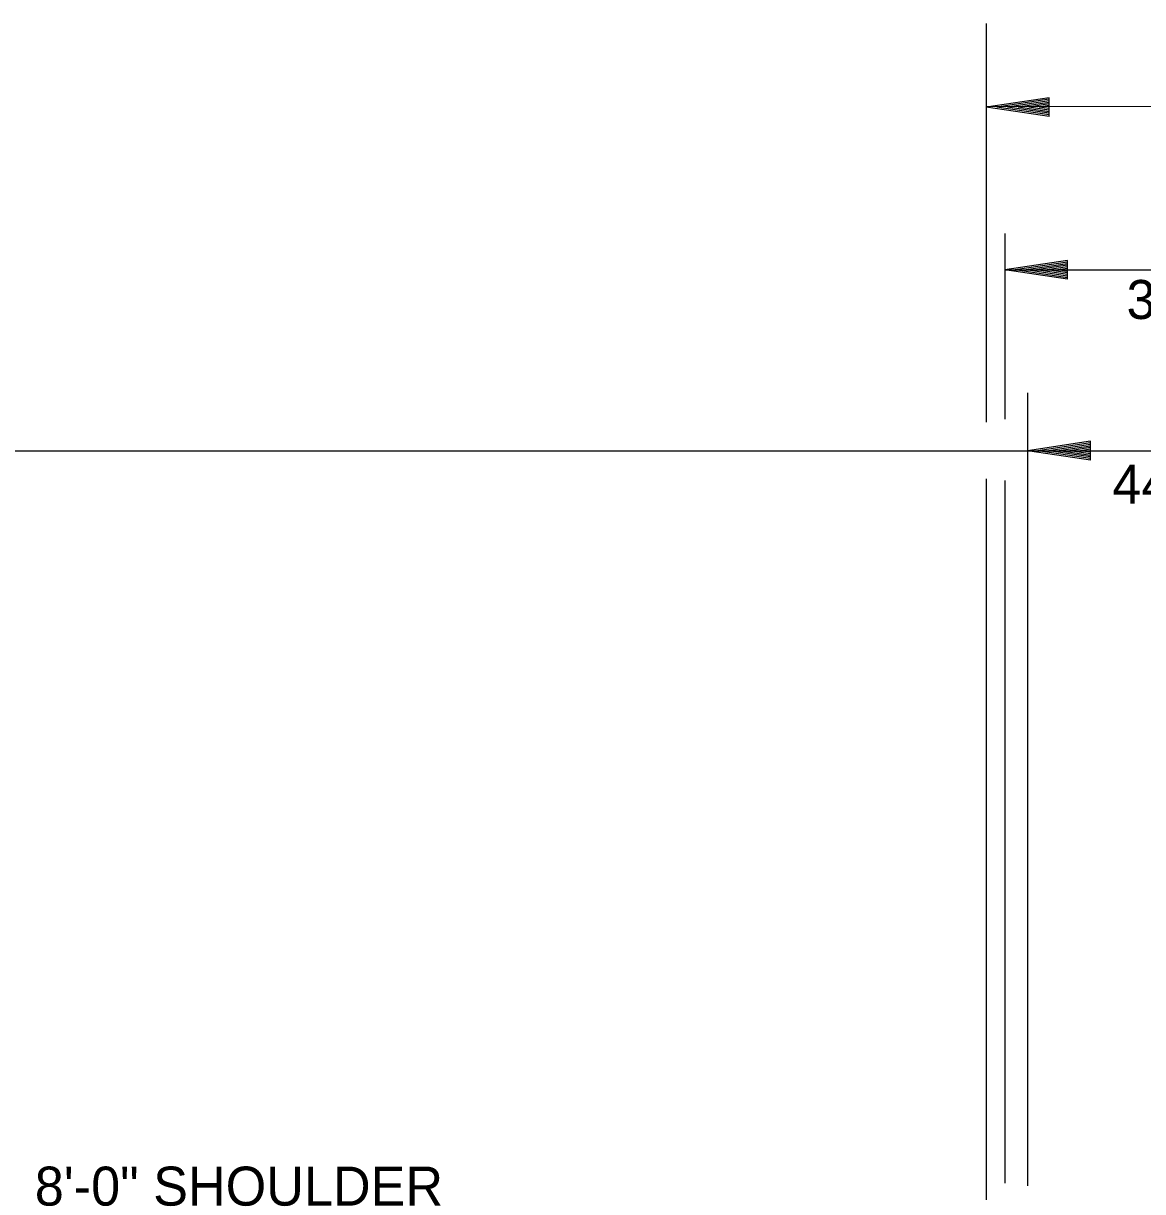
# Model space of a CAD drawing. Extents: x 714919 to 718439, y 1619644 to 1621844.
# Drawn here: x 716609 to 717039.4, y 1620836.2 to 1621285.5 of the extents above; entities that cross this region are included whole.
import ezdxf

# ---------------------------------------------------------------- set-up
doc = ezdxf.new("R2010")
doc.units = 0
doc.layers.add('Default', color=7, linetype='Continuous')

msp = doc.modelspace()

# ---------------------------------------------------------------- linework, layer by layer
at = {"layer": 'Default'}
for p, q in [((716979.24, 1621285.47), (716979.24, 1621132.15)), ((717003.41, 1621256.89), (716979.24, 1621253.27)), ((717003.41, 1621256.29), (716983.27, 1621253.27)), ((717003.41, 1621255.66), (716987.44, 1621253.27)), ((717003.41, 1621249.64), (717003.41, 1621256.89)), ((716979.24, 1621253.65), (717541.27, 1621252.35)), ((717003.41, 1621249.64), (716979.24, 1621253.27)), ((717003.41, 1621250.25), (716983.27, 1621253.27)), ((717003.41, 1621250.87), (716987.44, 1621253.27)), ((717003.41, 1621255.06), (716991.46, 1621253.27)), ((717003.41, 1621251.47), (716991.46, 1621253.27)), ((717003.41, 1621254.46), (716995.55, 1621253.27)), ((717003.41, 1621252.1), (716995.55, 1621253.27)), ((717003.41, 1621253.83), (716999.58, 1621253.27)), ((717003.41, 1621252.7), (716999.58, 1621253.27)), ((716986.36, 1621204.66), (716986.36, 1621133.24)), ((717010.53, 1621194.28), (716986.36, 1621190.66)), ((717010.53, 1621193.68), (716990.39, 1621190.66)), ((717010.53, 1621193.05), (716994.56, 1621190.66)), ((717010.53, 1621192.45), (716998.58, 1621190.66)), ((717010.53, 1621187.03), (717010.53, 1621194.28)), ((717010.53, 1621187.03), (716986.36, 1621190.66)), ((716986.36, 1621190.66), (717532.47, 1621190.66)), ((717010.53, 1621187.64), (716990.39, 1621190.66)), ((717010.53, 1621188.26), (716994.56, 1621190.66)), ((717010.53, 1621188.87), (716998.58, 1621190.66)), ((717010.53, 1621191.85), (717002.67, 1621190.66)), ((717010.53, 1621189.49), (717002.67, 1621190.66)), ((717010.53, 1621191.22), (717006.7, 1621190.66)), ((717010.53, 1621190.09), (717006.7, 1621190.66)), ((716995.1, 1621143.37), (716995.1, 1620838.45)), ((716353.98, 1621121.11), (717538.89, 1621121.11)), ((717019.27, 1621124.73), (716995.1, 1621121.11)), ((717019.27, 1621117.48), (716995.1, 1621121.11)), ((717019.27, 1621124.13), (716999.13, 1621121.11)), ((717019.27, 1621118.09), (716999.13, 1621121.11)), ((717019.27, 1621123.51), (717003.3, 1621121.11)), ((717019.27, 1621118.71), (717003.3, 1621121.11)), ((717019.27, 1621122.9), (717007.33, 1621121.11)), ((717019.27, 1621119.32), (717007.33, 1621121.11)), ((717019.27, 1621122.3), (717011.42, 1621121.11)), ((717019.27, 1621119.94), (717011.42, 1621121.11)), ((717019.27, 1621121.67), (717015.44, 1621121.11)), ((717019.27, 1621120.55), (717015.44, 1621121.11)), ((717019.27, 1621117.48), (717019.27, 1621124.73)), ((716979.24, 1621110.34), (716979.24, 1620781.44)), ((716986.36, 1621109.61), (716986.36, 1620839.49))]:
    msp.add_line(p, q, dxfattribs=at)

# ---------------------------------------------------------------- texts
for s, p in [('330 LBS. PER SQ. YD. & TACK COAT', (717033.17, 1621171.78)), ('440 LBS. PER SQ. YD. & TACK COAT', (717027.71, 1621100.8)), ('8\'-0" SHOULDER', (716613.44, 1620830.8))]:
    msp.add_text(s, height=15, dxfattribs=at).set_placement(p)

doc.saveas('drawing.dxf')
